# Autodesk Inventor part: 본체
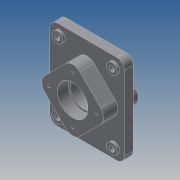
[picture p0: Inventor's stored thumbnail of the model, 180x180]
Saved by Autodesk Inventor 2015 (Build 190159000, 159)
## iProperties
Created: 2026-07
Part Number: 본체
Material: 일반
Document SubType Name: Modeling
Designer: USER
Density: 1 g/cm^3
Appearance: 기본값
Author: USER
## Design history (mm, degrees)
sketch "스케치1"
  geometry: L1 (0, 70.711)-(-70.711, 0); L2 (-70.711, 0)-(0, -70.711); L3 (0, -70.711)-(70.711, 0); L4 (70.711, 0)-(0, 70.711); L5 (75, 90)-(-75, 90); L6 (-75, 90)-(-75, -90); L7 (-75, -90)-(75, -90); L8 (75, -90)-(75, 90); L9 (75, 90)-(-75, -90); L10 (-75, 90)-(75, -90); 3 further points
  constraints: 20 end point, 4 midpoint, 4 parallel, 2 perpendicular, 2 vertical alignment, 1 horizontal, 1 horizontal alignment
  dimensions: "d6" = 100 distance of L1.start L1.end; "d8" = 100 distance between parallel lines of L1 L3; "d9" = 150 distance of L5.start L5.end; "d10" = 180 distance of L7.end L5.start
extrude "돌출1" new body sketch "스케치1" distance "d11" = 23; taper "d12" = 0 deg
extrude "돌출2" join sketch "스케치1" distance "d13" = 18; taper "d14" = 0 deg
sketch "스케치2"
  geometry: L1 (-75, 90)-(75, -90) reference; L2 (0, 70.711)-(70.711, 0) reference; L3 (70.711, 0)-(0, -70.711) reference; L4 (0, -70.711)-(-70.711, 0) reference; L5 (-70.711, 0)-(0, 70.711) reference; 1 further point
extrude "돌출3" join sketch "스케치2" distance "d15" = 29; taper "d16" = 0 deg
fillet "모깎기1" dims "d17" = 20
sketch "스케치3"
  geometry: C1 r 31 at (0, 0); 1 further point
  constraints: 1 centre point, 1 coincident
  dimensions: "d18" = 62 diameter of C1
extrude "돌출4" cut sketch "스케치3" distance "d19" = 22; taper "d20" = 0 deg
sketch "스케치4"
  geometry: C1 r 31 at (0, 0); 1 further point
  constraints: 1 centre point, 1 coincident
  dimensions: "d21" = 62 diameter of C1
extrude "돌출5" cut sketch "스케치4" distance "d22" = 22; taper "d23" = 0 deg
hole "구멍1" diameter "d26" = 54; stored, may be unused: countersink angle "d30" = 90 deg, drill point angle "d32" = 118 deg; dims "d24" = 10, "d25" = 10, "d27" = 6, "d28" = 4, "d29" = 2, "d31" = 8
fillet "모깎기2" dims "d33" = 15
sketch "스케치5"
  geometry: L1 (0, 0)-(48, 0)
  constraints: 2 end point, 1 horizontal
  dimensions: "d34" = 48 distance of L1.start L1.end
hole "구멍2" sketch "스케치5" at (48, 0) diameter "d35" = 4.917; stored, may be unused: countersink angle "d39" = 90 deg, drill point angle "d41" = 118 deg; dims "d36" = 10, "d37" = 4, "d38" = 2, "d40" = 13
node "작업 평면1"
sketch "스케치6"
  geometry: L1 (75, -75)-(75, 75) reference; L2 (60, 90)-(-60, 90) reference; C1 r 11 at (55, 70); 1 further point
  constraints: 1 centre point
  dimensions: "d45" = 22 diameter of C1; "d46" = 20 distance from line of L1 C1.centre; "d47" = 20 distance from line of L2 C1.centre
extrude "돌출6" join sketch "스케치6" distance "d48" = 5; taper "d49" = 0 deg
hole "구멍3" diameter "d52" = 11; stored, may be unused: countersink angle "d56" = 90 deg, drill point angle "d58" = 0 deg; dims "d50" = 10, "d51" = 10, "d53" = 11, "d54" = 4, "d55" = 2, "d57" = 13
node "솔리드1"
pattern_circular "원형 패턴1" dims angle "d43" = 360 deg
mirror "대칭1"
pattern_linear "직사각형 패턴1"
node "투영된 루프1"
